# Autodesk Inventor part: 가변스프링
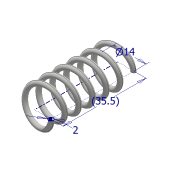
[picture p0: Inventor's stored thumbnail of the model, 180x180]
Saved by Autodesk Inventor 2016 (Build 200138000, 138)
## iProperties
Created: 2020-02
Part Number: 가변스프링
Material: 일반
Document SubType Name: Modeling
Designer: Administrator
Density: 1 g/cm^3
Appearance: 기본값
Mass: 0.819106 g
Surface Area: 16.6202 cm^2
Volume: 0.819106 cm^3
Author: Administrator
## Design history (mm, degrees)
sketch "스케치1"
  geometry: L1 (0, 0)-(7, 0); L2 (7, 0)-(7, 35.5); L3 (7, 35.5)-(0, 35.5); L4 (0, 35.5)-(0, 0); C1 r 1 at (7, 0)
  constraints: 8 end point, 2 parallel, 1 centre point, 1 coincident, 1 horizontal, 1 perpendicular
  dimensions: "d0" = 2 diameter of C1; "d1" = 35.5 distance of L1.end L2.end (derived); "d2" = 14 diameter of L2 L4
feature "코일1" sketch "스케치1" pitch "d3" = 10; turns "d5" = 6; dims "d4" = 35.5 (= d1), "d6" = 0, angle "d7" = 90 deg, angle "d8" = 90 deg, "d9" = 0, "d10" = 0
sketch "스케치2"
  geometry: L1 (-14.259, 12.495)-(13.827, 12.495); L2 (13.827, 12.495)-(13.827, -10.19); L3 (13.827, -10.19)-(-14.259, -10.19); L4 (-14.259, -10.19)-(-14.259, 12.495); 1 further point
  constraints: 8 end point, 2 parallel, 1 horizontal, 1 perpendicular
extrude "돌출1" cut sketch "스케치2" distance "d11" = 10; taper "d12" = 0 deg
node "작업 평면1"
sketch "스케치3"
  geometry: L1 (-8.556, 12.423)-(20.467, 12.423); L2 (20.467, 12.423)-(20.467, -13.575); L3 (20.467, -13.575)-(-8.556, -13.575); L4 (-8.556, -13.575)-(-8.556, 12.423); 1 further point
  constraints: 8 end point, 2 parallel, 1 horizontal, 1 perpendicular
extrude "돌출2" cut sketch "스케치3" distance "d14" = 10; taper "d15" = 0 deg
node "솔리드1"
other parameters: "d13" = 90 deg
